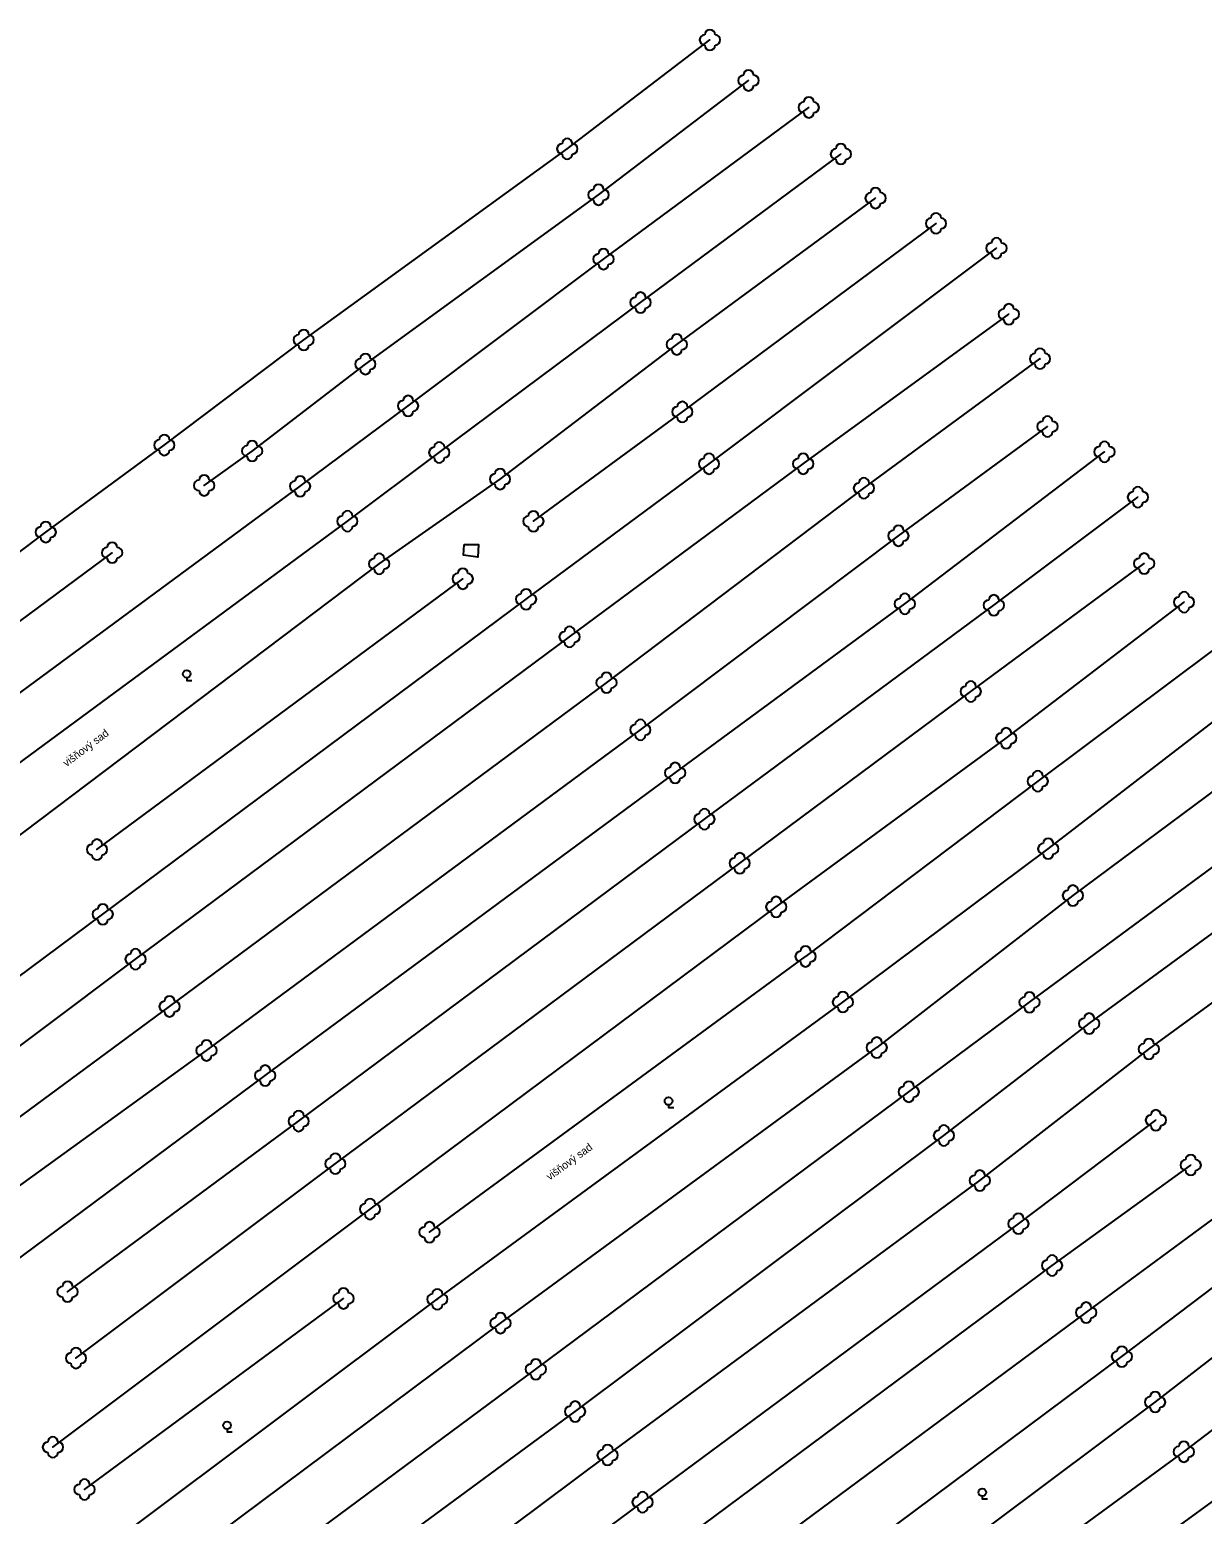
# Model space of a CAD drawing. Extents: x -577457 to -568404, y -1208466 to -1201387.
# Drawn here: x -569548.1 to -569434.2, y -1204305 to -1204160.7 of the extents above; entities that cross this region are included whole.
import ezdxf

# ---------------------------------------------------------------- set-up
doc = ezdxf.new("R2010")
doc.units = 0
for name, color, linetype in [('ZELEŇ', 7, 'Continuous'), ('ZN_DOPLŇKOVÉ', 7, 'Continuous'), ('ZN_KULTUR', 7, 'Continuous')]:
    doc.layers.add(name, color=color, linetype=linetype)

msp = doc.modelspace()

# ---------------------------------------------------------------- linework, layer by layer
at = {"layer": 'ZELEŇ'}
for points in [[(-569546.58, -1204209.56), (-569535.06, -1204201.1), (-569521.52, -1204190.89), (-569495.92, -1204172.32), (-569482.06, -1204161.74)], [(-569526.53, -1204201.68), (-569515.53, -1204193.23), (-569492.88, -1204176.78), (-569478.31, -1204165.67)], [(-569521.87, -1204205.11), (-569511.38, -1204197.3), (-569492.4, -1204183.03), (-569472.46, -1204168.29)], [(-569517.28, -1204208.5), (-569508.35, -1204201.82), (-569488.8, -1204187.26), (-569469.34, -1204172.82)], [(-569514.19, -1204212.64), (-569502.45, -1204204.41), (-569485.28, -1204191.32), (-569465.97, -1204177.1)], [(-569499.21, -1204208.51), (-569484.74, -1204197.88), (-569460.1, -1204179.56)], [(-569499.92, -1204216.09), (-569482.15, -1204202.92), (-569454.23, -1204181.97)], [(-569495.69, -1204219.74), (-569473, -1204202.92), (-569453.03, -1204188.39)], [(-569492.11, -1204224.19), (-569467.1, -1204205.29), (-569450, -1204192.71)], [(-569488.82, -1204228.77), (-569463.75, -1204209.91), (-569449.27, -1204199.3)], [(-569531.19, -1204205.02), (-569526.53, -1204201.68)], [(-569485.44, -1204232.96), (-569463.13, -1204216.53), (-569443.74, -1204201.76)], [(-569581.61, -1204249.39), (-569559.87, -1204233.12), (-569521.87, -1204205.11)], [(-569482.6, -1204237.45), (-569454.48, -1204216.67), (-569440.49, -1204206.16)], [(-569578.6, -1204254.13), (-569553.76, -1204235.38), (-569517.28, -1204208.5)], [(-569588.16, -1204240.49), (-569566.14, -1204224.26), (-569546.58, -1204209.56)], [(-569584.85, -1204245.06), (-569562.53, -1204228.16), (-569540.13, -1204211.56)], [(-569419.62, -1204211.37), (-569433.11, -1204220.96), (-569450.22, -1204233.76), (-569472.77, -1204250.79)], [(-569575.46, -1204258.67), (-569550.3, -1204239.92), (-569514.19, -1204212.64)], [(-569479.17, -1204241.74), (-569456.73, -1204225.05), (-569439.88, -1204212.62)], [(-569469.14, -1204255.22), (-569449.2, -1204240.32), (-569429.5, -1204225.14), (-569412.99, -1204212.85)], [(-569541.6, -1204240.41), (-569506.07, -1204214.09)], [(-569569.17, -1204267.6), (-569541.04, -1204246.7), (-569499.92, -1204216.09)], [(-569475.62, -1204245.98), (-569453.28, -1204229.59), (-569436.01, -1204216.37)], [(-569410.2, -1204217.66), (-569426.78, -1204229.98), (-569446.8, -1204244.88), (-569465.86, -1204259.65)], [(-569565.83, -1204272.04), (-569537.85, -1204251.06), (-569495.69, -1204219.74)], [(-569562.52, -1204276.3), (-569534.55, -1204255.65), (-569492.11, -1204224.19)], [(-569462.75, -1204263.94), (-569451.02, -1204255.25), (-569423.05, -1204234.6), (-569409.19, -1204224.06)], [(-569559.24, -1204280.38), (-569530.96, -1204259.92), (-569488.82, -1204228.77)], [(-569459.33, -1204268.19), (-569445.22, -1204257.32), (-569420.36, -1204239.1), (-569408.42, -1204230.33)], [(-569555.94, -1204285.14), (-569525.26, -1204262.37), (-569485.44, -1204232.96)], [(-569455.84, -1204272.57), (-569439.43, -1204259.79), (-569416.87, -1204243.33), (-569404.94, -1204234.5)], [(-569544.46, -1204283.37), (-569522.01, -1204266.79), (-569482.6, -1204237.45)], [(-569543.64, -1204289.82), (-569518.45, -1204270.93), (-569479.17, -1204241.74)], [(-569545.88, -1204298.48), (-569515.08, -1204275.34), (-569475.62, -1204245.98)], [(-569509.3, -1204277.59), (-569472.77, -1204250.79)], [(-569539.43, -1204307.26), (-569508.54, -1204284.11), (-569469.14, -1204255.22)], [(-569536.22, -1204311.66), (-569502.4, -1204286.42), (-569465.86, -1204259.65)], [(-569532.62, -1204315.85), (-569498.97, -1204290.91), (-569462.75, -1204263.94)], [(-569452.1, -1204276.76), (-569438.74, -1204266.71)], [(-569529.28, -1204320.13), (-569495.16, -1204295.02), (-569459.33, -1204268.19)], [(-569448.83, -1204280.82), (-569435.36, -1204271.06)], [(-569525.6, -1204324.34), (-569492, -1204299.24), (-569455.84, -1204272.57)], [(-569445.52, -1204285.4), (-569431.98, -1204275.4)], [(-569522.4, -1204328.91), (-569488.6, -1204303.82), (-569452.1, -1204276.76)], [(-569442.04, -1204289.68), (-569428.58, -1204279.46)], [(-569518.95, -1204332.97), (-569484.98, -1204307.7), (-569448.83, -1204280.82)], [(-569438.82, -1204294.09), (-569425.17, -1204283.53)], [(-569542.81, -1204302.59), (-569517.65, -1204284.02)], [(-569513.29, -1204335.79), (-569481.87, -1204312.34), (-569445.52, -1204285.4)], [(-569436.03, -1204298.92), (-569420.12, -1204286.83)], [(-569509.69, -1204339.96), (-569478.58, -1204316.92), (-569442.04, -1204289.68)], [(-569506.49, -1204344.39), (-569475.36, -1204321.47), (-569438.82, -1204294.09)], [(-569503.94, -1204349.64), (-569472.45, -1204325.62), (-569436.03, -1204298.92)], [(-569500.04, -1204353.29), (-569488.52, -1204344.74), (-569446.84, -1204313.67), (-569432.18, -1204302.99)]]:
    msp.add_lwpolyline(points, dxfattribs=at)
for centre in [(-569482.06, -1204161.74), (-569478.31, -1204165.67), (-569472.46, -1204168.29), (-569495.92, -1204172.32), (-569469.34, -1204172.82), (-569492.88, -1204176.78), (-569465.97, -1204177.1), (-569460.1, -1204179.56), (-569454.23, -1204181.97), (-569492.4, -1204183.03), (-569488.8, -1204187.26), (-569453.03, -1204188.39), (-569521.52, -1204190.89), (-569485.28, -1204191.32), (-569450, -1204192.71), (-569515.53, -1204193.23), (-569511.38, -1204197.3), (-569484.74, -1204197.88), (-569449.27, -1204199.3), (-569535.06, -1204201.1), (-569526.53, -1204201.68), (-569508.35, -1204201.82), (-569482.15, -1204202.92), (-569473, -1204202.92), (-569443.74, -1204201.76), (-569502.45, -1204204.41), (-569531.19, -1204205.02), (-569521.87, -1204205.11), (-569467.1, -1204205.29), (-569440.49, -1204206.16), (-569517.28, -1204208.5), (-569499.21, -1204208.51), (-569546.58, -1204209.56), (-569463.75, -1204209.91), (-569540.13, -1204211.56), (-569514.19, -1204212.64), (-569439.88, -1204212.62), (-569506.07, -1204214.09), (-569499.92, -1204216.09), (-569463.13, -1204216.53), (-569454.48, -1204216.67), (-569436.01, -1204216.37), (-569495.69, -1204219.74), (-569492.11, -1204224.19), (-569456.73, -1204225.05), (-569488.82, -1204228.77), (-569453.28, -1204229.59), (-569485.44, -1204232.96), (-569450.22, -1204233.76), (-569482.6, -1204237.45), (-569541.6, -1204240.41), (-569449.2, -1204240.32), (-569479.17, -1204241.74), (-569446.8, -1204244.88), (-569475.62, -1204245.98), (-569541.04, -1204246.7), (-569537.85, -1204251.06), (-569472.77, -1204250.79), (-569534.55, -1204255.65), (-569469.14, -1204255.22), (-569451.02, -1204255.25), (-569445.22, -1204257.32), (-569530.96, -1204259.92), (-569465.86, -1204259.65), (-569439.43, -1204259.79), (-569525.26, -1204262.37), (-569462.75, -1204263.94), (-569522.01, -1204266.79), (-569438.74, -1204266.71), (-569459.33, -1204268.19), (-569518.45, -1204270.93), (-569435.36, -1204271.06), (-569455.84, -1204272.57), (-569515.08, -1204275.34), (-569509.3, -1204277.59), (-569452.1, -1204276.76), (-569448.83, -1204280.82), (-569544.46, -1204283.37), (-569517.65, -1204284.02), (-569508.54, -1204284.11), (-569502.4, -1204286.42), (-569445.52, -1204285.4), (-569442.04, -1204289.68), (-569543.64, -1204289.82), (-569498.97, -1204290.91), (-569495.16, -1204295.02), (-569438.82, -1204294.09), (-569545.88, -1204298.48), (-569492, -1204299.24), (-569436.03, -1204298.92), (-569542.81, -1204302.59), (-569488.6, -1204303.82)]:
    msp.add_circle(centre, 0.0005, dxfattribs=at)
for centre, start, end in [((-569482.56, -1204161.74), 90, 270), ((-569482.06, -1204161.24), 0, 180), ((-569481.56, -1204161.74), 270, 90), ((-569482.06, -1204162.24), 180, 360), ((-569478.81, -1204165.67), 90, 270), ((-569478.31, -1204165.17), 0, 180), ((-569477.81, -1204165.67), 270, 90), ((-569478.31, -1204166.17), 180, 360), ((-569472.96, -1204168.29), 90, 270), ((-569472.46, -1204167.79), 0, 180), ((-569471.96, -1204168.29), 270, 90), ((-569472.46, -1204168.79), 180, 360), ((-569495.92, -1204171.82), 0, 180), ((-569496.42, -1204172.32), 90, 270), ((-569495.92, -1204172.82), 180, 360), ((-569495.42, -1204172.32), 270, 90), ((-569469.84, -1204172.82), 90, 270), ((-569469.34, -1204172.32), 0, 180), ((-569468.84, -1204172.82), 270, 90), ((-569469.34, -1204173.32), 180, 360), ((-569493.38, -1204176.78), 90, 270), ((-569492.88, -1204176.28), 0, 180), ((-569492.38, -1204176.78), 270, 90), ((-569466.47, -1204177.1), 90, 270), ((-569465.97, -1204176.6), 0, 180), ((-569465.47, -1204177.1), 270, 90), ((-569492.88, -1204177.28), 180, 360), ((-569465.97, -1204177.6), 180, 360), ((-569460.1, -1204179.06), 0, 180), ((-569460.6, -1204179.56), 90, 270), ((-569459.6, -1204179.56), 270, 90), ((-569460.1, -1204180.06), 180, 360), ((-569454.73, -1204181.97), 90, 270), ((-569454.23, -1204181.47), 0, 180), ((-569453.73, -1204181.97), 270, 90), ((-569492.9, -1204183.03), 90, 270), ((-569492.4, -1204182.53), 0, 180), ((-569491.9, -1204183.03), 270, 90), ((-569454.23, -1204182.47), 180, 360), ((-569492.4, -1204183.53), 180, 360), ((-569489.3, -1204187.26), 90, 270), ((-569488.8, -1204186.76), 0, 180), ((-569488.3, -1204187.26), 270, 90), ((-569488.8, -1204187.76), 180, 360), ((-569453.53, -1204188.39), 90, 270), ((-569453.03, -1204187.89), 0, 180), ((-569452.53, -1204188.39), 270, 90), ((-569521.52, -1204190.39), 0, 180), ((-569453.03, -1204188.89), 180, 360), ((-569522.02, -1204190.89), 90, 270), ((-569521.52, -1204191.39), 180, 360), ((-569521.02, -1204190.89), 270, 90), ((-569485.78, -1204191.32), 90, 270), ((-569485.28, -1204190.82), 0, 180), ((-569484.78, -1204191.32), 270, 90), ((-569516.03, -1204193.23), 90, 270), ((-569515.53, -1204192.73), 0, 180), ((-569515.03, -1204193.23), 270, 90), ((-569485.28, -1204191.82), 180, 360), ((-569450.5, -1204192.71), 90, 270), ((-569450, -1204192.21), 0, 180), ((-569449.5, -1204192.71), 270, 90), ((-569515.53, -1204193.73), 180, 360), ((-569450, -1204193.21), 180, 360), ((-569511.88, -1204197.3), 90, 270), ((-569511.38, -1204196.8), 0, 180), ((-569510.88, -1204197.3), 270, 90), ((-569484.74, -1204197.38), 0, 180), ((-569511.38, -1204197.8), 180, 360), ((-569485.24, -1204197.88), 90, 270), ((-569484.74, -1204198.38), 180, 360), ((-569484.24, -1204197.88), 270, 90), ((-569449.77, -1204199.3), 90, 270), ((-569449.27, -1204198.8), 0, 180), ((-569448.77, -1204199.3), 270, 90), ((-569535.06, -1204200.6), 0, 180), ((-569449.27, -1204199.8), 180, 360), ((-569535.56, -1204201.1), 90, 270), ((-569535.06, -1204201.6), 180, 360), ((-569534.56, -1204201.1), 270, 90), ((-569527.03, -1204201.68), 90, 270), ((-569526.53, -1204201.18), 0, 180), ((-569526.03, -1204201.68), 270, 90), ((-569508.85, -1204201.82), 90, 270), ((-569508.35, -1204201.32), 0, 180), ((-569507.85, -1204201.82), 270, 90), ((-569444.24, -1204201.76), 90, 270), ((-569443.74, -1204201.26), 0, 180), ((-569443.24, -1204201.76), 270, 90), ((-569526.53, -1204202.18), 180, 360), ((-569508.35, -1204202.32), 180, 360), ((-569482.65, -1204202.92), 90, 270), ((-569482.15, -1204202.42), 0, 180), ((-569481.65, -1204202.92), 270, 90), ((-569473.5, -1204202.92), 90, 270), ((-569473, -1204202.42), 0, 180), ((-569472.5, -1204202.92), 270, 90), ((-569443.74, -1204202.26), 180, 360), ((-569531.69, -1204205.02), 90, 270), ((-569531.19, -1204204.52), 0, 180), ((-569530.69, -1204205.02), 270, 90), ((-569521.87, -1204204.61), 0, 180), ((-569502.95, -1204204.41), 90, 270), ((-569502.45, -1204203.91), 0, 180), ((-569501.95, -1204204.41), 270, 90), ((-569482.15, -1204203.42), 180, 360), ((-569473, -1204203.42), 180, 360), ((-569467.1, -1204204.79), 0, 180), ((-569531.19, -1204205.52), 180, 360), ((-569522.37, -1204205.11), 90, 270), ((-569521.87, -1204205.61), 180, 360), ((-569521.37, -1204205.11), 270, 90), ((-569502.45, -1204204.91), 180, 360), ((-569467.6, -1204205.29), 90, 270), ((-569467.1, -1204205.79), 180, 360), ((-569466.6, -1204205.29), 270, 90), ((-569440.99, -1204206.16), 90, 270), ((-569440.49, -1204205.66), 0, 180), ((-569439.99, -1204206.16), 270, 90), ((-569440.49, -1204206.66), 180, 360), ((-569546.58, -1204209.06), 0, 180), ((-569517.78, -1204208.5), 90, 270), ((-569517.28, -1204208), 0, 180), ((-569516.78, -1204208.5), 270, 90), ((-569499.71, -1204208.51), 90, 270), ((-569499.21, -1204208.01), 0, 180), ((-569498.71, -1204208.51), 270, 90), ((-569547.08, -1204209.56), 90, 270), ((-569546.58, -1204210.06), 180, 360), ((-569546.08, -1204209.56), 270, 90), ((-569517.28, -1204209), 180, 360), ((-569499.21, -1204209.01), 180, 360), ((-569464.25, -1204209.91), 90, 270), ((-569463.75, -1204209.41), 0, 180), ((-569463.25, -1204209.91), 270, 90), ((-569540.63, -1204211.56), 90, 270), ((-569540.13, -1204211.06), 0, 180), ((-569539.63, -1204211.56), 270, 90), ((-569514.19, -1204212.14), 0, 180), ((-569463.75, -1204210.41), 180, 360), ((-569439.88, -1204212.12), 0, 180), ((-569540.13, -1204212.06), 180, 360), ((-569514.69, -1204212.64), 90, 270), ((-569514.19, -1204213.14), 180, 360), ((-569513.69, -1204212.64), 270, 90), ((-569506.07, -1204213.59), 0, 180), ((-569440.38, -1204212.62), 90, 270), ((-569439.88, -1204213.12), 180, 360), ((-569439.38, -1204212.62), 270, 90), ((-569506.57, -1204214.09), 90, 270), ((-569506.07, -1204214.59), 180, 360), ((-569505.57, -1204214.09), 270, 90), ((-569500.42, -1204216.09), 90, 270), ((-569499.92, -1204215.59), 0, 180), ((-569499.42, -1204216.09), 270, 90), ((-569463.63, -1204216.53), 90, 270), ((-569463.13, -1204216.03), 0, 180), ((-569462.63, -1204216.53), 270, 90), ((-569454.48, -1204216.17), 0, 180), ((-569436.51, -1204216.37), 90, 270), ((-569436.01, -1204215.87), 0, 180), ((-569435.51, -1204216.37), 270, 90), ((-569499.92, -1204216.59), 180, 360), ((-569463.13, -1204217.03), 180, 360), ((-569454.98, -1204216.67), 90, 270), ((-569454.48, -1204217.17), 180, 360), ((-569453.98, -1204216.67), 270, 90), ((-569436.01, -1204216.87), 180, 360), ((-569495.69, -1204219.24), 0, 180), ((-569496.19, -1204219.74), 90, 270), ((-569495.69, -1204220.24), 180, 360), ((-569495.19, -1204219.74), 270, 90), ((-569492.11, -1204223.69), 0, 180), ((-569492.61, -1204224.19), 90, 270), ((-569492.11, -1204224.69), 180, 360), ((-569491.61, -1204224.19), 270, 90), ((-569457.23, -1204225.05), 90, 270), ((-569456.73, -1204224.55), 0, 180), ((-569456.23, -1204225.05), 270, 90), ((-569456.73, -1204225.55), 180, 360), ((-569489.32, -1204228.77), 90, 270), ((-569488.82, -1204228.27), 0, 180), ((-569488.32, -1204228.77), 270, 90), ((-569453.78, -1204229.59), 90, 270), ((-569453.28, -1204229.09), 0, 180), ((-569452.78, -1204229.59), 270, 90), ((-569488.82, -1204229.27), 180, 360), ((-569453.28, -1204230.09), 180, 360), ((-569485.44, -1204232.46), 0, 180), ((-569485.94, -1204232.96), 90, 270), ((-569484.94, -1204232.96), 270, 90), ((-569450.72, -1204233.76), 90, 270), ((-569450.22, -1204233.26), 0, 180), ((-569449.72, -1204233.76), 270, 90), ((-569485.44, -1204233.46), 180, 360), ((-569450.22, -1204234.26), 180, 360), ((-569483.1, -1204237.45), 90, 270), ((-569482.6, -1204236.95), 0, 180), ((-569482.1, -1204237.45), 270, 90), ((-569482.6, -1204237.95), 180, 360), ((-569542.1, -1204240.41), 90, 270), ((-569541.6, -1204239.91), 0, 180), ((-569541.1, -1204240.41), 270, 90), ((-569449.7, -1204240.32), 90, 270), ((-569449.2, -1204239.82), 0, 180), ((-569448.7, -1204240.32), 270, 90), ((-569541.6, -1204240.91), 180, 360), ((-569479.67, -1204241.74), 90, 270), ((-569479.17, -1204241.24), 0, 180), ((-569478.67, -1204241.74), 270, 90), ((-569449.2, -1204240.82), 180, 360), ((-569479.17, -1204242.24), 180, 360), ((-569447.3, -1204244.88), 90, 270), ((-569446.8, -1204244.38), 0, 180), ((-569446.3, -1204244.88), 270, 90), ((-569541.54, -1204246.7), 90, 270), ((-569541.04, -1204246.2), 0, 180), ((-569540.54, -1204246.7), 270, 90), ((-569476.12, -1204245.98), 90, 270), ((-569475.62, -1204245.48), 0, 180), ((-569475.12, -1204245.98), 270, 90), ((-569446.8, -1204245.38), 180, 360), ((-569541.04, -1204247.2), 180, 360), ((-569475.62, -1204246.48), 180, 360), ((-569538.35, -1204251.06), 90, 270), ((-569537.85, -1204250.56), 0, 180), ((-569537.35, -1204251.06), 270, 90), ((-569473.27, -1204250.79), 90, 270), ((-569472.77, -1204250.29), 0, 180), ((-569472.27, -1204250.79), 270, 90), ((-569537.85, -1204251.56), 180, 360), ((-569472.77, -1204251.29), 180, 360), ((-569534.55, -1204255.15), 0, 180), ((-569469.64, -1204255.22), 90, 270), ((-569469.14, -1204254.72), 0, 180), ((-569468.64, -1204255.22), 270, 90), ((-569451.52, -1204255.25), 90, 270), ((-569451.02, -1204254.75), 0, 180), ((-569450.52, -1204255.25), 270, 90), ((-569535.05, -1204255.65), 90, 270), ((-569534.55, -1204256.15), 180, 360), ((-569534.05, -1204255.65), 270, 90), ((-569469.14, -1204255.72), 180, 360), ((-569451.02, -1204255.75), 180, 360), ((-569445.22, -1204256.82), 0, 180), ((-569445.72, -1204257.32), 90, 270), ((-569445.22, -1204257.82), 180, 360), ((-569444.72, -1204257.32), 270, 90), ((-569530.96, -1204259.42), 0, 180), ((-569466.36, -1204259.65), 90, 270), ((-569465.86, -1204259.15), 0, 180), ((-569465.36, -1204259.65), 270, 90), ((-569439.93, -1204259.79), 90, 270), ((-569439.43, -1204259.29), 0, 180), ((-569438.93, -1204259.79), 270, 90), ((-569531.46, -1204259.92), 90, 270), ((-569530.96, -1204260.42), 180, 360), ((-569530.46, -1204259.92), 270, 90), ((-569465.86, -1204260.15), 180, 360), ((-569439.43, -1204260.29), 180, 360), ((-569525.76, -1204262.37), 90, 270), ((-569525.26, -1204261.87), 0, 180), ((-569524.76, -1204262.37), 270, 90), ((-569525.26, -1204262.87), 180, 360), ((-569463.25, -1204263.94), 90, 270), ((-569462.75, -1204263.44), 0, 180), ((-569462.25, -1204263.94), 270, 90), ((-569462.75, -1204264.44), 180, 360), ((-569522.51, -1204266.79), 90, 270), ((-569522.01, -1204266.29), 0, 180), ((-569521.51, -1204266.79), 270, 90), ((-569439.24, -1204266.71), 90, 270), ((-569438.74, -1204266.21), 0, 180), ((-569438.24, -1204266.71), 270, 90), ((-569522.01, -1204267.29), 180, 360), ((-569459.83, -1204268.19), 90, 270), ((-569459.33, -1204267.69), 0, 180), ((-569458.83, -1204268.19), 270, 90), ((-569438.74, -1204267.21), 180, 360), ((-569459.33, -1204268.69), 180, 360), ((-569518.95, -1204270.93), 90, 270), ((-569518.45, -1204270.43), 0, 180), ((-569517.95, -1204270.93), 270, 90), ((-569435.86, -1204271.06), 90, 270), ((-569435.36, -1204270.56), 0, 180), ((-569434.86, -1204271.06), 270, 90), ((-569518.45, -1204271.43), 180, 360), ((-569456.34, -1204272.57), 90, 270), ((-569455.84, -1204272.07), 0, 180), ((-569455.34, -1204272.57), 270, 90), ((-569435.36, -1204271.56), 180, 360), ((-569455.84, -1204273.07), 180, 360), ((-569515.58, -1204275.34), 90, 270), ((-569515.08, -1204274.84), 0, 180), ((-569514.58, -1204275.34), 270, 90), ((-569515.08, -1204275.84), 180, 360), ((-569509.3, -1204277.09), 0, 180), ((-569452.6, -1204276.76), 90, 270), ((-569452.1, -1204276.26), 0, 180), ((-569451.6, -1204276.76), 270, 90), ((-569509.8, -1204277.59), 90, 270), ((-569509.3, -1204278.09), 180, 360), ((-569508.8, -1204277.59), 270, 90), ((-569452.1, -1204277.26), 180, 360), ((-569449.33, -1204280.82), 90, 270), ((-569448.83, -1204280.32), 0, 180), ((-569448.33, -1204280.82), 270, 90), ((-569544.46, -1204282.87), 0, 180), ((-569448.83, -1204281.32), 180, 360), ((-569544.96, -1204283.37), 90, 270), ((-569544.46, -1204283.87), 180, 360), ((-569543.96, -1204283.37), 270, 90), ((-569518.15, -1204284.02), 90, 270), ((-569517.65, -1204283.52), 0, 180), ((-569517.15, -1204284.02), 270, 90), ((-569509.04, -1204284.11), 90, 270), ((-569508.54, -1204283.61), 0, 180), ((-569508.04, -1204284.11), 270, 90), ((-569517.65, -1204284.52), 180, 360), ((-569508.54, -1204284.61), 180, 360), ((-569446.02, -1204285.4), 90, 270), ((-569445.52, -1204284.9), 0, 180), ((-569445.02, -1204285.4), 270, 90), ((-569502.9, -1204286.42), 90, 270), ((-569502.4, -1204285.92), 0, 180), ((-569501.9, -1204286.42), 270, 90), ((-569445.52, -1204285.9), 180, 360), ((-569502.4, -1204286.92), 180, 360), ((-569544.14, -1204289.82), 90, 270), ((-569543.64, -1204289.32), 0, 180), ((-569543.14, -1204289.82), 270, 90), ((-569442.54, -1204289.68), 90, 270), ((-569442.04, -1204289.18), 0, 180), ((-569441.54, -1204289.68), 270, 90), ((-569543.64, -1204290.32), 180, 360), ((-569499.47, -1204290.91), 90, 270), ((-569498.97, -1204290.41), 0, 180), ((-569498.47, -1204290.91), 270, 90), ((-569442.04, -1204290.18), 180, 360), ((-569498.97, -1204291.41), 180, 360), ((-569495.16, -1204294.52), 0, 180), ((-569439.32, -1204294.09), 90, 270), ((-569438.82, -1204293.59), 0, 180), ((-569438.32, -1204294.09), 270, 90), ((-569495.66, -1204295.02), 90, 270), ((-569494.66, -1204295.02), 270, 90), ((-569438.82, -1204294.59), 180, 360), ((-569495.16, -1204295.52), 180, 360), ((-569546.38, -1204298.48), 90, 270), ((-569545.88, -1204297.98), 0, 180), ((-569545.38, -1204298.48), 270, 90), ((-569492, -1204298.74), 0, 180), ((-569436.03, -1204298.42), 0, 180), ((-569545.88, -1204298.98), 180, 360), ((-569492.5, -1204299.24), 90, 270), ((-569492, -1204299.74), 180, 360), ((-569491.5, -1204299.24), 270, 90), ((-569436.53, -1204298.92), 90, 270), ((-569436.03, -1204299.42), 180, 360), ((-569435.53, -1204298.92), 270, 90), ((-569543.31, -1204302.59), 90, 270), ((-569542.81, -1204302.09), 0, 180), ((-569542.31, -1204302.59), 270, 90), ((-569542.81, -1204303.09), 180, 360), ((-569489.1, -1204303.82), 90, 270), ((-569488.6, -1204303.32), 0, 180), ((-569488.1, -1204303.82), 270, 90), ((-569488.6, -1204304.32), 180, 360)]:
    msp.add_arc(centre, 0.5, start, end, dxfattribs=at)
at = {"layer": 'ZN_DOPLŇKOVÉ'}
msp.add_lwpolyline([(-569505.94, -1204210.78), (-569504.55, -1204210.78), (-569504.59, -1204212.01), (-569506.01, -1204211.79), (-569505.94, -1204210.78)], dxfattribs=at)
at = {"layer": 'ZN_KULTUR'}
for points in [[(-569532.88, -1204223.72), (-569532.88, -1204223.97), (-569532.38, -1204223.97)], [(-569486.08, -1204265.23), (-569486.08, -1204265.48), (-569485.58, -1204265.48)], [(-569528.96, -1204296.74), (-569528.96, -1204296.99), (-569528.46, -1204296.99)], [(-569455.61, -1204303.25), (-569455.61, -1204303.5), (-569455.11, -1204303.5)]]:
    msp.add_lwpolyline(points, dxfattribs=at)
for centre in [(-569532.88, -1204223.34), (-569486.08, -1204264.85), (-569528.96, -1204296.36), (-569455.61, -1204302.87)]:
    msp.add_circle(centre, 0.375, dxfattribs=at)

# ---------------------------------------------------------------- texts
at = {"layer": 'ZELEŇ'}
for rotation, p in [(37.0699, (-569544.56, -1204232.4)), (36.2507, (-569497.62, -1204272.58))]:
    msp.add_text('višňový sad', height=0.75, rotation=rotation, dxfattribs=at).set_placement(p)

doc.saveas('drawing.dxf')
